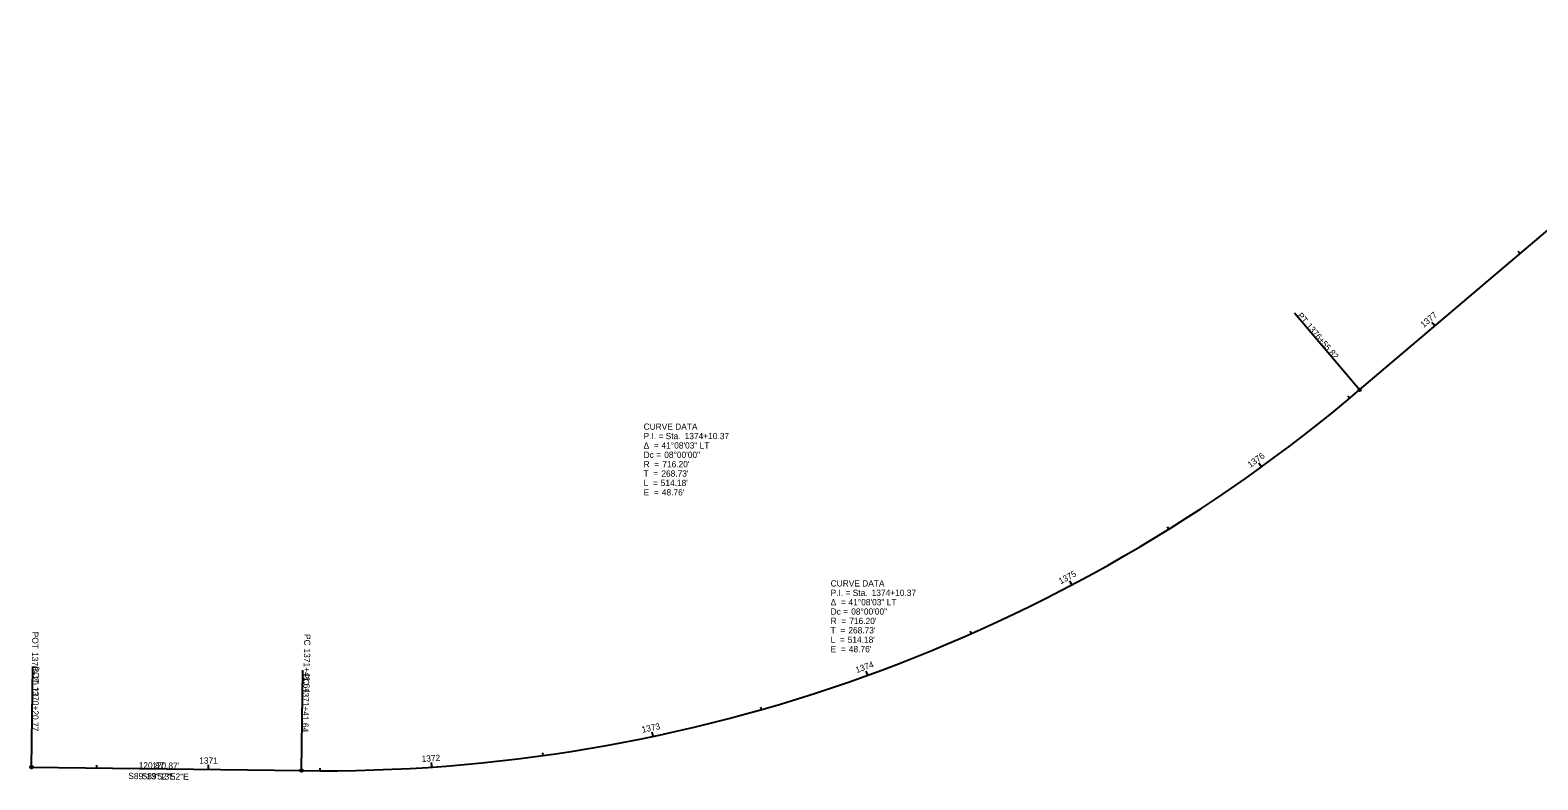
# Model space of a CAD drawing. Extents: x 155009 to 156350, y 371331 to 371956.
# Drawn here: x 155009 to 155684, y 371331 to 371667 of the extents above; entities that cross this region are included whole.
import ezdxf

# ---------------------------------------------------------------- set-up
doc = ezdxf.new("R2010")
doc.units = 0
for name, color, linetype in [('Default', 7, 'Continuous'), ('GE_X_Alignment', 7, 'Continuous'), ('GE_X_Alignment_1000_Curve_Data', 7, 'Continuous'), ('GE_X_Alignment_1000_Stations', 7, 'Continuous'), ('GE_X_Alignment_100_Curve_Data', 7, 'Continuous'), ('GE_X_Alignment_100_Stations', 7, 'Continuous'), ('GE_X_Alignment_500_Curve_Data', 7, 'Continuous'), ('GE_X_Alignment_500_Stations', 7, 'Continuous')]:
    doc.layers.add(name, color=color, linetype=linetype)

msp = doc.modelspace()

# ---------------------------------------------------------------- linework, layer by layer
at = {"layer": 'Default'}
msp.add_arc((155140.27, 372051.56), 716.2, 269.23101, 310.36525, dxfattribs=at)
at = {"layer": 'GE_X_Alignment'}
for p, q in [((155604.12, 371505.86), (155793.55, 371666.88)), ((155009.79, 371337.04), (155130.65, 371335.42))]:
    msp.add_line(p, q, dxfattribs=at)
msp.add_arc((155140.27, 372051.56), 716.2, 269.23101, 310.36525, dxfattribs=at)
at = {"layer": 'GE_X_Alignment_1000_Stations'}
for p, q in [((155604.12, 371505.86), (155574.97, 371540.15)), ((155475.39, 371418.6), (155474.83, 371419.66)), ((155009.79, 371337.04), (155010.4, 371382.04)), ((155130.65, 371335.42), (155131.26, 371380.42))]:
    msp.add_line(p, q, dxfattribs=at)
for centre in [(155604.12, 371505.86), (155009.79, 371337.04), (155130.65, 371335.42)]:
    msp.add_circle(centre, 0.6, dxfattribs=at)
at = {"layer": 'GE_X_Alignment_100_Stations'}
for p, q in [((155675.88, 371566.86), (155675.1, 371567.77)), ((155604.12, 371505.86), (155574.97, 371540.15)), ((155637.78, 371534.47), (155636.48, 371536)), ((155599.67, 371502.11), (155598.9, 371503.03)), ((155560.22, 371471.4), (155559.05, 371473.02)), ((155518.73, 371443.52), (155518.1, 371444.54)), ((155475.39, 371418.6), (155474.46, 371420.37)), ((155430.42, 371396.77), (155429.94, 371397.86)), ((155009.79, 371337.04), (155010.4, 371382.04)), ((155130.65, 371335.42), (155131.26, 371380.42)), ((155384.04, 371378.12), (155383.36, 371380)), ((155336.47, 371362.76), (155336.14, 371363.91)), ((155287.95, 371350.75), (155287.53, 371352.7)), ((155238.7, 371342.15), (155238.54, 371343.34)), ((155039.02, 371336.65), (155039.04, 371337.85)), ((155089.02, 371335.98), (155089.04, 371337.98)), ((155139.01, 371335.36), (155139.02, 371336.56)), ((155188.98, 371337.01), (155188.84, 371339.01))]:
    msp.add_line(p, q, dxfattribs=at)
for centre in [(155604.12, 371505.86), (155009.79, 371337.04), (155130.65, 371335.42)]:
    msp.add_circle(centre, 0.6, dxfattribs=at)
at = {"layer": 'GE_X_Alignment_500_Stations'}
for p, q in [((155604.12, 371505.86), (155574.97, 371540.15)), ((155637.78, 371534.47), (155637, 371535.39)), ((155560.22, 371471.4), (155559.52, 371472.37)), ((155475.39, 371418.6), (155474.46, 371420.37)), ((155009.79, 371337.04), (155010.4, 371382.04)), ((155130.65, 371335.42), (155131.26, 371380.42)), ((155384.04, 371378.12), (155383.63, 371379.25)), ((155287.95, 371350.75), (155287.7, 371351.92)), ((155089.02, 371335.98), (155089.03, 371337.18)), ((155188.98, 371337.01), (155188.89, 371338.21))]:
    msp.add_line(p, q, dxfattribs=at)
for centre in [(155604.12, 371505.86), (155009.79, 371337.04), (155130.65, 371335.42)]:
    msp.add_circle(centre, 0.6, dxfattribs=at)

# ---------------------------------------------------------------- texts
at = {"layer": 'GE_X_Alignment_1000_Curve_Data'}
for s, p in [('CURVE DATA', (155367.39, 371417.84)), ('Δ  = ', (155367.39, 371409.44)), ('P.I. = Sta. ', (155367.39, 371413.64)), ('41°08\'03" LT', (155375.41, 371409.44)), ('1374+10.37', (155385.75, 371413.64)), ('Dc = ', (155367.39, 371405.24)), ('R  = ', (155367.39, 371401.04)), ("716.20'", (155375.75, 371401.04)), ('08°00\'00"', (155376.62, 371405.24)), ('T  = ', (155367.39, 371396.84)), ("268.73'", (155375.32, 371396.84)), ('L  = ', (155367.39, 371392.64)), ('E  = ', (155367.39, 371388.44)), ("514.18'", (155375.03, 371392.64)), ("48.76'", (155375.54, 371388.44))]:
    msp.add_text(s, height=2.8, dxfattribs=at).set_placement(p)
at = {"layer": 'GE_X_Alignment_1000_Stations'}
for s, rotation, p in [('PT', 310.36518, (155576.02, 371538.99)), ('1376+55.82', 310.36518, (155579.96, 371534.35)), ('POT', 269.23101, (155010.45, 371382.06)), ('PC', 269.23101, (155131.29, 371379.04)), ('1370+20.77', 269.23101, (155010.32, 371372.93)), ('1371+41.64', 269.23101, (155131.2, 371372.52)), ("120.87'", 359.23101, (155063.74, 371336.37)), ('S89°13\'52"E', 359.23101, (155059.09, 371331.58))]:
    msp.add_text(s, height=2.8, rotation=rotation, dxfattribs=at).set_placement(p)
at = {"layer": 'GE_X_Alignment_100_Curve_Data'}
for s, p in [('CURVE DATA', (155367.39, 371417.84)), ('Δ  = ', (155367.39, 371409.44)), ('P.I. = Sta. ', (155367.39, 371413.64)), ('41°08\'03" LT', (155375.41, 371409.44)), ('1374+10.37', (155385.75, 371413.64)), ('Dc = ', (155367.39, 371405.24)), ('R  = ', (155367.39, 371401.04)), ("716.20'", (155375.75, 371401.04)), ('08°00\'00"', (155376.62, 371405.24)), ('T  = ', (155367.39, 371396.84)), ("268.73'", (155375.32, 371396.84)), ('L  = ', (155367.39, 371392.64)), ('E  = ', (155367.39, 371388.44)), ("514.18'", (155375.03, 371392.64)), ("48.76'", (155375.54, 371388.44))]:
    msp.add_text(s, height=2.8, dxfattribs=at).set_placement(p)
at = {"layer": 'GE_X_Alignment_100_Stations'}
for s, rotation, p in [('PT', 310.36518, (155576.02, 371538.99)), ('1377', 40.36518, (155632.76, 371533.55)), ('1376+55.82', 310.36518, (155579.96, 371534.35)), ('1376', 35.89967, (155555.19, 371470.9)), ('1375', 27.8997, (155470.33, 371418.8)), ('POT', 269.23101, (155010.14, 371397.64)), ('PC', 269.23101, (155131.83, 371396.62)), ('1370+20.77', 269.23101, (155010.02, 371388.51)), ('1371+41.64', 269.23101, (155131.74, 371390.09)), ('1374', 19.89973, (155379.11, 371379.04)), ('1373', 11.89976, (155283.16, 371352.34)), ("120.87'", 359.23101, (155057.74, 371336.44)), ('1371', 359.23101, (155084.85, 371338.58)), ('1372', 3.89979, (155184.45, 371339.26)), ('S89°13\'52"E', 359.23101, (155053.09, 371331.66))]:
    msp.add_text(s, height=2.8, rotation=rotation, dxfattribs=at).set_placement(p)
at = {"layer": 'GE_X_Alignment_500_Curve_Data'}
for s, p in [('CURVE DATA', (155283.69, 371488)), ('P.I. = Sta. ', (155283.69, 371483.8)), ('1374+10.37', (155302.06, 371483.8)), ('Δ  = ', (155283.69, 371479.6)), ('Dc = ', (155283.69, 371475.4)), ('41°08\'03" LT', (155291.72, 371479.6)), ('08°00\'00"', (155292.93, 371475.4)), ('R  = ', (155283.69, 371471.2)), ("716.20'", (155292.06, 371471.2)), ('T  = ', (155283.69, 371467)), ('L  = ', (155283.69, 371462.8)), ("514.18'", (155291.34, 371462.8)), ("268.73'", (155291.63, 371467)), ('E  = ', (155283.69, 371458.6)), ("48.76'", (155291.85, 371458.6))]:
    msp.add_text(s, height=2.8, dxfattribs=at).set_placement(p)
at = {"layer": 'GE_X_Alignment_500_Stations'}
for s, rotation, p in [('PT', 310.36518, (155576.02, 371538.99)), ('1376+55.82', 310.36518, (155579.96, 371534.35)), ('1375', 27.8997, (155470.33, 371418.8)), ('POT', 269.23101, (155010.45, 371382.06)), ('PC', 269.23101, (155131.29, 371379.04)), ('1370+20.77', 269.23101, (155010.32, 371372.93)), ('1371+41.64', 269.23101, (155131.2, 371372.52)), ("120.87'", 359.23101, (155063.74, 371336.37)), ('S89°13\'52"E', 359.23101, (155059.09, 371331.58))]:
    msp.add_text(s, height=2.8, rotation=rotation, dxfattribs=at).set_placement(p)

doc.saveas('drawing.dxf')
